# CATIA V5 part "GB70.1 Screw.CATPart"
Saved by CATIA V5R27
Part number: 螺钉_PowerCopy
Bounding box of the stored display mesh (mm): x -5 to 5, y -4.99 to 4.99, z -6 to 55
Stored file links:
  C:\Users\姚一鸣\Desktop\超级副本\GB70.1 螺钉\GB70.1 Screw.CATPart
  C:\Users\姚一鸣\Desktop\超级副本\GB70.1 螺钉\DesignTable.xlsx
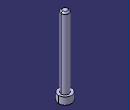
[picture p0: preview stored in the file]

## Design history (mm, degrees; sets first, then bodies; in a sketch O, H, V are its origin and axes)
Parameters
  `圆柱头直径` = 10 mm {design table}
  `圆柱头厚度` = 6 mm {design table}
  s = 5 mm {design table}
  t = 3 mm {design table}
  v = 0.6 mm {design table}
  b = 1.2 mm {design table}
  `公称直径` = 6 mm {design table}
  `螺钉长度` = 55 mm {design table}
AxisSystem1: origin (0, 0, 0), X (1, 0, 0), Y (0, 1, 0), Z (0, 0, 1)
Set1 "定位元素"
  Plane1: type Normal, Curve Line1, RefPoint Point1, Ratio 0
  Point1: (0, 0, 0), in AxisSystem1
Body1 (main body)
  Sketch1 on Plane1, origin (0, 0, 0), H (1, 0, 0), V (0, 1, 0)
    circle A1 centre (0, 0) radius 5
    radius A1 = 5 {= `圆柱头直径` /2}
  Pad1: profile Sketch1, direction (0, 0, -1), length 6 {= `圆柱头厚度`}
  Fillet1: radius 0.6 {= v}, on end face of Pad1
  Sketch2 on Plane1, origin (0, 0, 0), H (1, 0, 0), V (0, 1, 0)
    circle A1 centre (0, 0) radius 3
    radius A1 = 3 {= `公称直径` /2}
  Pad2: profile Sketch2, direction (0, 0, 1), length 55 {= `螺钉长度`}
  Chamfer1: length 1.2 {= b}, angle 45, on end face of Pad2
  Set2
    Line1: type PtDir, RefPoint Point1, Direction (0, 0, 1), Start 0, End 20
  Sketch3 on end face of Pad1, origin (0, 0, -6), H (1, 0, 0), V (0, -1, 0)
    point P1 (0, 0)
    point P2 (2.5, 0)
    construction circle A1 centre (0, 0) radius 2.8868
    construction circle A2 centre (0, 0) radius 2.5
    point P3 (2.5, -1.4434)
    point P4 (2.5, 1.4434)
    point P5 (0, 2.8868)
    point P6 (-2.5, 1.4434)
    point P7 (-2.5, -1.4434)
    point P8 (0, -2.8868)
    line L1 (2.5, -1.4434) -> (2.5, 1.4434)
    line L2 (2.5, 1.4434) -> (0, 2.8868)
    line L3 (0, 2.8868) -> (-2.5, 1.4434)
    line L4 (-2.5, 1.4434) -> (-2.5, -1.4434)
    line L5 (-2.5, -1.4434) -> (0, -2.8868)
    line L6 (0, -2.8868) -> (2.5, -1.4434)
    construction line L7 (0, 0) -> (2.5, 0)
    reference projected point E1 (0, 0) from axis of face of Pad1 from Sketch1.A1
    distance L1 L4 = 5 {= s}
    coincidence: A1 P3, A1 P4, A1 P5, A1 P6, A1 P7, A1 P8, P1 H, P1 E1
    tangency: A2 L1, A2 L2, A2 L3, A2 L4, A2 L5, A2 L6
    midpoint: P2 L1
    horizontal: L7 H
  Pocket1: profile Sketch3, direction (0, 0, 1), length 3 {= t}
Relations
  design table "GB70.1 螺钉参数表", configuration 68, drives `圆柱头直径`, `圆柱头厚度`, s, t, v, b, `公称直径`, `螺钉长度`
